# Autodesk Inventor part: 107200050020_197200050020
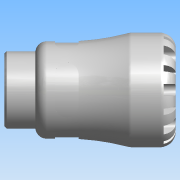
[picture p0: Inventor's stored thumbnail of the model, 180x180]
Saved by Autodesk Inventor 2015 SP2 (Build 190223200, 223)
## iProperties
Created: 2016-12
Part Number: 107200050020_197200050020
Material: PVC-Piping
Description: PLASSON MALE INTEGRAL BRASS THREAD 50X2" SERIES 1
Document SubType Name: Modeling
Designer: KIM
Mass: 61.7504 g
Surface Area: 140.097 cm^2
Volume: 44.1074 cm^3
Density: 1.4 g/cm^3
Appearance: Smooth - White
Author: KIM
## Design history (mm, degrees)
derived "1072.ipt"
feature "Solid1::1072.ipt"
tag "TaggingFeature1"
body "Solid1"
other parameters: "d0" = 127, "d1" = 34.02, "d3" = 62.5, "d4" = 85, "d6" = 81, "d8" = 72.25, "d13" = 9, "d14" = 9, "d15" = 0, "d17" = 360 deg, "d19" = 8 deg, "d20" = 1, "d21" = 1, "d22" = 8 deg, "d24" = 0, "d26" = 360 deg, "d32" = 8.5, "d33" = 8.5, "d34" = 57.296, "d38" = 23, "d39" = 1.71888, "d42" = 17.5, "d43" = 11.5, "d45" = 17.64, "d46" = 0, "d59" = 360 deg, "d61" = 14.875, "d62" = 1, "d64" = 0, "d65" = 0.85, "d68" = 7.14286, "E_" = 85, "H_" = 127, "l_" = 81, "R_" = 57.296, "l_2" = 23, "d9" = 11.25, "d11" = 85, "d12" = 62.5
